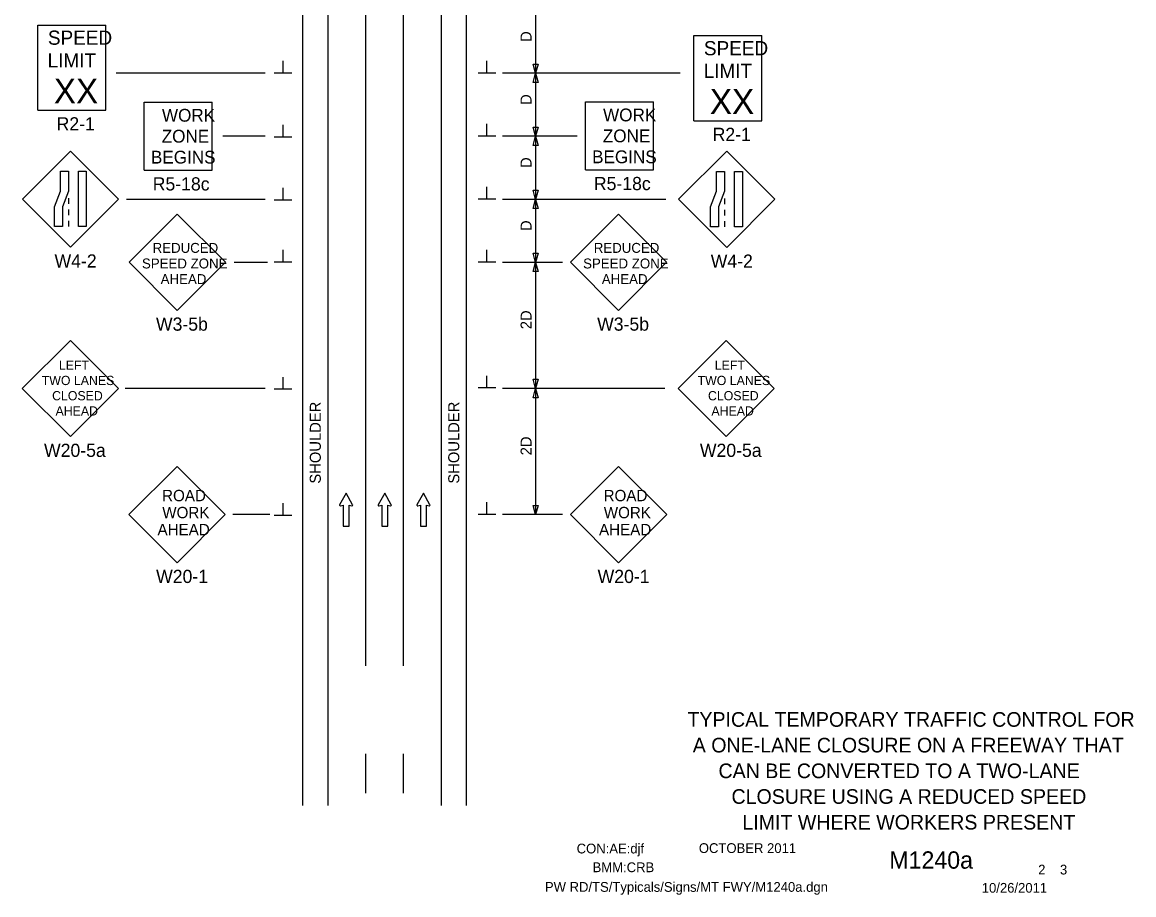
# Model space of a CAD drawing. Extents: x 16576 to 19504, y 5728 to 6974.
# Drawn here: x 17768 to 18473, y 5932 to 6485 of the extents above; entities that cross this region are included whole.
import ezdxf

# ---------------------------------------------------------------- set-up
doc = ezdxf.new("R2010")
doc.units = 0
for name, color, linetype in [('ALI_LEGAL_EX', 7, 'Continuous'), ('BORDER', 7, 'Continuous'), ('BORDER_SIGNAL_WO', 7, 'Continuous'), ('MT_SCRATCH_LEVEL_E', 7, 'Continuous'), ('PAVT_EDGE_EX', 7, 'Continuous'), ('TRAFFIC_SIGNS_PR', 7, 'Continuous'), ('TYPICAL_TEXT_DIMEN_PR', 7, 'Continuous')]:
    doc.layers.add(name, color=color, linetype=linetype)

msp = doc.modelspace()

# ---------------------------------------------------------------- linework, layer by layer
at = {"layer": 'ALI_LEGAL_EX'}
for p, q in [((17985.63, 6921.33), (17985.63, 6077.19)), ((18009.63, 6921.33), (18009.63, 6077.19))]:
    msp.add_line(p, q, dxfattribs=at)
for points in [[(17985.63, 6421.33), (17985.63, 6396.33)], [(18009.63, 6421.33), (18009.63, 6396.33)], [(17985.63, 6321.33), (17985.63, 6296.33)], [(18009.63, 6321.33), (18009.63, 6296.33)], [(17985.63, 6221.33), (17985.63, 6196.33)], [(18009.63, 6221.33), (18009.63, 6196.33)], [(17985.63, 6121.33), (17985.63, 6096.33)], [(18009.63, 6121.33), (18009.63, 6096.33)], [(17985.63, 6021.33), (17985.63, 5996.33)], [(18009.63, 6021.33), (18009.63, 5996.33)]]:
    msp.add_lwpolyline(points, dxfattribs=at)
at = {"layer": 'MT_SCRATCH_LEVEL_E'}
for p, q in [((17973.31, 6186.57), (17969.2, 6179.33)), ((17977.46, 6179.33), (17973.31, 6186.57)), ((17997.84, 6186.57), (17993.73, 6179.33)), ((18001.99, 6179.33), (17997.84, 6186.57)), ((18022.4, 6186.57), (18018.29, 6179.33)), ((18026.55, 6179.33), (18022.4, 6186.57)), ((17969.68, 6178.65), (17971.46, 6178.96)), ((17971.46, 6178.96), (17971.46, 6165.71)), ((17975.2, 6165.71), (17975.2, 6178.96)), ((17975.2, 6178.96), (17976.98, 6178.65)), ((17994.21, 6178.65), (17995.99, 6178.96)), ((17995.99, 6178.96), (17995.99, 6165.71)), ((17999.73, 6165.71), (17999.73, 6178.96)), ((17999.73, 6178.96), (18001.51, 6178.65)), ((18018.77, 6178.65), (18020.55, 6178.96)), ((18020.55, 6178.96), (18020.55, 6165.71)), ((18024.29, 6165.71), (18024.29, 6178.96)), ((18024.29, 6178.96), (18026.07, 6178.65)), ((17971.46, 6165.71), (17975.2, 6165.71)), ((17995.99, 6165.71), (17999.73, 6165.71)), ((18020.55, 6165.71), (18024.29, 6165.71))]:
    msp.add_line(p, q, dxfattribs=at)
for centre, start, end in [((17969.61, 6179.11), 150.42484, 279.96381), ((17977.05, 6179.11), 260.03619, 29.77312), ((17994.14, 6179.11), 150.42484, 279.96381), ((18001.58, 6179.11), 260.03619, 29.77312), ((18018.7, 6179.11), 150.42484, 279.96381), ((18026.14, 6179.11), 260.03619, 29.77312)]:
    msp.add_arc(centre, 0.463, start, end, dxfattribs=at)
at = {"layer": 'PAVT_EDGE_EX'}
for p, q in [((17945.63, 6921.33), (17945.63, 5988.51)), ((17961.63, 6921.33), (17961.63, 5988.51)), ((18033.63, 6921.33), (18033.63, 5988.51)), ((18049.63, 6921.33), (18049.63, 5988.51))]:
    msp.add_line(p, q, dxfattribs=at)
at = {"layer": 'TRAFFIC_SIGNS_PR'}
for p, q in [((17777.46, 6483.68), (17820.66, 6483.68)), ((17777.46, 6429.68), (17777.46, 6483.68)), ((17820.66, 6429.68), (17820.66, 6483.68)), ((18194.01, 6476.99), (18237.21, 6476.99)), ((18194.01, 6422.99), (18194.01, 6476.99)), ((18237.21, 6422.99), (18237.21, 6476.99)), ((17845.1, 6391.56), (17845.1, 6434.76)), ((17845.1, 6434.76), (17888.3, 6434.76)), ((17888.3, 6391.56), (17888.3, 6434.76)), ((18125.22, 6391.77), (18125.22, 6434.97)), ((18125.22, 6434.97), (18168.42, 6434.97)), ((18168.42, 6391.77), (18168.42, 6434.97)), ((17777.46, 6429.68), (17820.66, 6429.68)), ((18194.01, 6422.99), (18237.21, 6422.99)), ((17798.33, 6403.73), (17767.79, 6373.19)), ((17828.88, 6373.19), (17798.33, 6403.73)), ((18215, 6403.64), (18184.46, 6373.1)), ((18245.55, 6373.1), (18215, 6403.64)), ((17845.1, 6391.56), (17888.3, 6391.56)), ((18125.22, 6391.77), (18168.42, 6391.77)), ((17796.93, 6373.74), (17796.93, 6370.14)), ((18213.6, 6373.65), (18213.6, 6370.05)), ((17767.79, 6373.19), (17798.33, 6342.64)), ((17796.93, 6366.54), (17796.93, 6362.94)), ((17798.33, 6342.64), (17828.88, 6373.19)), ((18184.46, 6373.1), (18215, 6342.55)), ((18213.6, 6366.45), (18213.6, 6362.85)), ((18215, 6342.55), (18245.55, 6373.1)), ((17796.93, 6359.34), (17796.93, 6355.74)), ((17866.12, 6363.7), (17835.57, 6333.15)), ((17896.66, 6333.15), (17866.12, 6363.7)), ((18146.24, 6363.7), (18115.69, 6333.15)), ((18176.79, 6333.15), (18146.24, 6363.7)), ((18213.6, 6359.25), (18213.6, 6355.65)), ((17835.57, 6333.15), (17866.12, 6302.6)), ((17866.12, 6302.6), (17896.66, 6333.15)), ((18115.69, 6333.15), (18146.24, 6302.6)), ((18146.24, 6302.6), (18176.79, 6333.15)), ((17798.2, 6283.6), (17767.65, 6253.06)), ((17828.74, 6253.06), (17798.2, 6283.6)), ((18214.66, 6283.6), (18184.11, 6253.06)), ((18245.2, 6253.06), (18214.66, 6283.6)), ((17767.65, 6253.06), (17798.2, 6222.51)), ((17798.2, 6222.51), (17828.74, 6253.06)), ((18184.11, 6253.06), (18214.66, 6222.51)), ((18214.66, 6222.51), (18245.2, 6253.06)), ((17865.97, 6203.6), (17835.42, 6173.06)), ((17896.51, 6173.06), (17865.97, 6203.6)), ((18146.32, 6203.6), (18115.77, 6173.06)), ((18176.86, 6173.06), (18146.32, 6203.6)), ((17835.42, 6173.06), (17865.97, 6142.51)), ((17865.97, 6142.51), (17896.51, 6173.06)), ((18115.77, 6173.06), (18146.32, 6142.51)), ((18146.32, 6142.51), (18176.86, 6173.06))]:
    msp.add_line(p, q, dxfattribs=at)
for points in [[(17796.93, 6390.89), (17796.93, 6378.31), (17793.17, 6368.32), (17793.17, 6355.74), (17788.11, 6355.74), (17788.11, 6368.32), (17791.87, 6378.31), (17791.87, 6390.89)], [(17808.33, 6390.89), (17808.33, 6355.74), (17803.28, 6355.74), (17803.28, 6390.89)], [(18213.6, 6390.8), (18213.6, 6378.22), (18209.84, 6368.23), (18209.84, 6355.65), (18204.78, 6355.65), (18204.78, 6368.23), (18208.55, 6378.22), (18208.55, 6390.8)], [(18225, 6390.8), (18225, 6355.65), (18219.95, 6355.65), (18219.95, 6390.8)]]:
    msp.add_lwpolyline(points, close=True, dxfattribs=at)
at = {"layer": 'TYPICAL_TEXT_DIMEN_PR'}
for p, q in [((18093.63, 6493.06), (18093.63, 6453.06)), ((17933.29, 6453.23), (17933.29, 6461.01)), ((18062.76, 6453.23), (18062.76, 6461.01)), ((18093.63, 6453.06), (18092.06, 6458.92)), ((18092.06, 6458.92), (18093.63, 6458.92)), ((18093.63, 6458.92), (18095.2, 6458.92)), ((18095.2, 6458.92), (18093.63, 6453.06)), ((17921.92, 6453.06), (17827.3, 6453.06)), ((17938.91, 6453.23), (17927.66, 6453.23)), ((18068.38, 6453.23), (18057.13, 6453.23)), ((18185.4, 6453.06), (18072.63, 6453.06)), ((18092.06, 6447.2), (18093.63, 6453.06)), ((18093.63, 6453.06), (18093.63, 6413.06)), ((18093.63, 6453.06), (18095.2, 6447.2)), ((18093.63, 6447.2), (18092.06, 6447.2)), ((18095.2, 6447.2), (18093.63, 6447.2)), ((17933.29, 6412.54), (17933.29, 6420.32)), ((18062.76, 6413.23), (18062.76, 6421.01)), ((18093.63, 6413.06), (18092.06, 6418.92)), ((18092.06, 6418.92), (18093.63, 6418.92)), ((18093.63, 6418.92), (18095.2, 6418.92)), ((18095.2, 6418.92), (18093.63, 6413.06)), ((17921.92, 6413.06), (17895.12, 6413.06)), ((17938.91, 6412.54), (17927.66, 6412.54)), ((18068.38, 6413.23), (18057.13, 6413.23)), ((18119.95, 6413.06), (18072.63, 6413.06)), ((18092.06, 6407.2), (18093.63, 6413.06)), ((18093.63, 6413.06), (18093.63, 6373.06)), ((18093.63, 6413.06), (18095.2, 6407.2)), ((18093.63, 6407.2), (18092.06, 6407.2)), ((18095.2, 6407.2), (18093.63, 6407.2)), ((18062.76, 6373.23), (18062.76, 6381.01)), ((17933.29, 6372.54), (17933.29, 6380.32)), ((18093.63, 6373.06), (18092.06, 6378.92)), ((18092.06, 6378.92), (18093.63, 6378.92)), ((18093.63, 6378.92), (18095.2, 6378.92)), ((18095.2, 6378.92), (18093.63, 6373.06)), ((17921.92, 6373.06), (17833.91, 6373.06)), ((17938.91, 6372.54), (17927.66, 6372.54)), ((18068.38, 6373.23), (18057.13, 6373.23)), ((18176.25, 6373.06), (18072.63, 6373.06)), ((18092.06, 6367.2), (18093.63, 6373.06)), ((18093.63, 6367.2), (18092.06, 6367.2)), ((18093.63, 6373.06), (18093.63, 6333.06)), ((18093.63, 6373.06), (18095.2, 6367.2)), ((18095.2, 6367.2), (18093.63, 6367.2)), ((17933.29, 6333.22), (17933.29, 6341)), ((18062.76, 6333.23), (18062.76, 6341.01)), ((18093.63, 6333.06), (18092.06, 6338.92)), ((18092.06, 6338.92), (18093.63, 6338.92)), ((18093.63, 6338.92), (18095.2, 6338.92)), ((18095.2, 6338.92), (18093.63, 6333.06)), ((17923.49, 6333.06), (17902.19, 6333.06)), ((17938.91, 6333.22), (17927.66, 6333.22)), ((18068.38, 6333.23), (18057.13, 6333.23)), ((18110.79, 6333.06), (18072.63, 6333.06)), ((18092.06, 6327.2), (18093.63, 6333.06)), ((18093.63, 6333.06), (18093.63, 6253.06)), ((18093.63, 6333.06), (18095.2, 6327.2)), ((18093.63, 6327.2), (18092.06, 6327.2)), ((18095.2, 6327.2), (18093.63, 6327.2)), ((18062.76, 6253.38), (18062.76, 6261.16)), ((17933.29, 6252.54), (17933.29, 6260.32)), ((18093.63, 6253.06), (18092.06, 6258.92)), ((18092.06, 6258.92), (18093.63, 6258.92)), ((18093.63, 6258.92), (18095.2, 6258.92)), ((18095.2, 6258.92), (18093.63, 6253.06)), ((17921.92, 6253.06), (17833.05, 6253.06)), ((17938.91, 6252.54), (17927.66, 6252.54)), ((18068.38, 6253.38), (18057.13, 6253.38)), ((18175.75, 6253.06), (18072.63, 6253.06)), ((18092.06, 6247.2), (18093.63, 6253.06)), ((18093.63, 6247.2), (18092.06, 6247.2)), ((18093.63, 6253.06), (18093.63, 6173.06)), ((18093.63, 6253.06), (18095.2, 6247.2)), ((18095.2, 6247.2), (18093.63, 6247.2)), ((17933.29, 6172.54), (17933.29, 6180.32)), ((18062.76, 6173.05), (18062.76, 6180.84)), ((18093.63, 6173.06), (18092.06, 6178.92)), ((18092.06, 6178.92), (18093.63, 6178.92)), ((18093.63, 6178.92), (18095.2, 6178.92)), ((18095.2, 6178.92), (18093.63, 6173.06)), ((17924.78, 6173.06), (17901.47, 6173.06)), ((17938.91, 6172.54), (17927.66, 6172.54)), ((18068.38, 6173.05), (18057.13, 6173.05)), ((18110.79, 6173.06), (18072.63, 6173.06))]:
    msp.add_line(p, q, dxfattribs=at)

# ---------------------------------------------------------------- texts
at = {"layer": 'BORDER'}
for s, p in [('TYPICAL TEMPORARY TRAFFIC CONTROL FOR', (18190.04, 6038.42)), ('A ONE-LANE CLOSURE ON A FREEWAY THAT', (18193.42, 6022.12)), ('CAN BE CONVERTED TO A TWO-LANE ', (18209.75, 6005.82)), ('CLOSURE USING A REDUCED SPEED', (18218.02, 5989.52)), ('LIMIT WHERE WORKERS PRESENT', (18224.92, 5973.22))]:
    msp.add_text(s, height=9.3, dxfattribs=at).set_placement(p)
at = {"layer": 'BORDER_SIGNAL_WO'}
for s, height, p in [('CON:AE:djf  ', 6.2, (18119.69, 5958.06)), ('    OCTOBER 2011    ', 6.2, (18188.08, 5958.34)), ('    M1240a   ', 11, (18301.86, 5948.38)), ('BMM:CRB   ', 6.2, (18129.81, 5946.17)), (' 2    3 ', 6.2, (18410.45, 5944.7)), ('PW RD/TS/Typicals/Signs/MT FWY/M1240a.dgn      ', 6.2, (18099.55, 5933.71)), ('10/26/2011    ', 6.2, (18376.93, 5933.13))]:
    msp.add_text(s, height=height, dxfattribs=at).set_placement(p)
at = {"layer": 'TRAFFIC_SIGNS_PR'}
for s, height, p in [('SPEED', 9, (17783.95, 6471.15)), ('SPEED', 9, (18200.5, 6464.46)), ('LIMIT', 9, (17783.76, 6456.75)), ('LIMIT', 9, (18200.32, 6450.06)), ('XX', 15.785, (17787.71, 6433.9)), ('XX', 15.785, (18204.27, 6427.22)), ('WORK', 8.119, (17856.35, 6422.35)), ('WORK', 8.119, (18136.47, 6422.56)), ('R2-1', 8.37, (17789.47, 6416.81)), ('ZONE', 8.119, (17856.21, 6409.07)), ('ZONE', 8.119, (18136.33, 6409.27)), ('R2-1', 8.37, (18206.03, 6410.12)), ('BEGINS', 8.119, (17849.38, 6395.78)), ('BEGINS', 8.119, (18129.5, 6395.99)), ('R5-18c', 8.37, (17850.51, 6378.69)), ('R5-18c', 8.37, (18130.63, 6378.9)), ('REDUCED', 6.3, (17850.43, 6339.12)), ('REDUCED', 6.3, (18130.55, 6339.12)), ('W4-2', 8.37, (17788.16, 6329.77)), ('W4-2', 8.37, (18204.83, 6329.68)), ('SPEED ZONE', 6.3, (17843.67, 6329.22)), ('SPEED ZONE', 6.3, (18123.79, 6329.22)), ('AHEAD', 6.3, (17855.55, 6319.32)), ('AHEAD', 6.3, (18135.67, 6319.32)), ('W3-5b', 8.37, (17852.56, 6289.73)), ('W3-5b', 8.37, (18132.69, 6289.73)), ('LEFT', 5.85, (17790.93, 6264.91)), ('LEFT', 5.85, (18207.39, 6264.91)), ('TWO LANES', 5.85, (17780.04, 6255.23)), ('TWO LANES', 5.85, (18196.5, 6255.23)), ('CLOSED', 5.85, (17786.62, 6245.56)), ('CLOSED', 5.85, (18203.08, 6245.56)), ('AHEAD', 5.85, (17788.81, 6235.88)), ('AHEAD', 5.85, (18205.27, 6235.88)), ('W20-5a', 8.37, (17781.48, 6209.64)), ('W20-5a', 8.37, (18197.94, 6209.64)), ('ROAD', 7.2, (17856.45, 6181.53)), ('ROAD', 7.2, (18136.8, 6181.53)), ('WORK', 7.2, (17856.57, 6170.74)), ('WORK', 7.2, (18136.92, 6170.74)), ('AHEAD', 7.2, (17853.55, 6159.94)), ('AHEAD', 7.2, (18133.9, 6159.94)), ('W20-1', 8.37, (17852.66, 6129.64)), ('W20-1', 8.37, (18133.01, 6129.64))]:
    msp.add_text(s, height=height, dxfattribs=at).set_placement(p)
at = {"layer": 'TYPICAL_TEXT_DIMEN_PR'}
for s, p in [('D', (18091.08, 6472.97)), ('D', (18091.08, 6432.97)), ('D', (18091.08, 6392.97)), ('D', (18091.08, 6352.97)), ('2D', (18091.08, 6290.67)), ('SHOULDER', (17957.25, 6192.68)), ('SHOULDER', (18045.15, 6192.68)), ('2D', (18091.08, 6210.67))]:
    msp.add_text(s, height=7, rotation=90, dxfattribs=at).set_placement(p)

doc.saveas('drawing.dxf')
